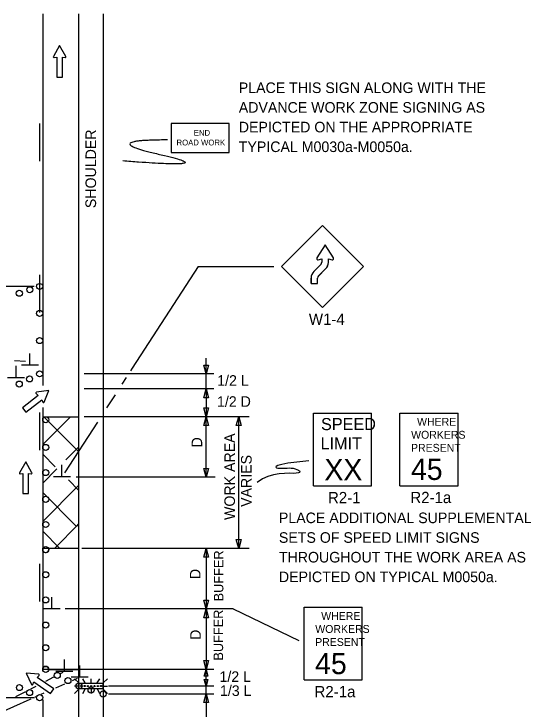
# Model space of a CAD drawing. Extents: x 16750 to 18306, y 5932 to 6925.
# Drawn here: x 17080.6 to 17422.4, y 6458.2 to 6917.6 of the extents above; entities that cross this region are included whole.
import ezdxf

# ---------------------------------------------------------------- set-up
doc = ezdxf.new("R2010")
doc.units = 0
for name, color, linetype in [('BORDER', 7, 'Continuous'), ('Level 3', 7, 'Continuous'), ('MT_SCRATCH_LEVEL_A', 7, 'Continuous'), ('MT_SCRATCH_LEVEL_E', 7, 'Continuous'), ('MT_STAGE_1A_NOTES', 7, 'Continuous'), ('PAVT_EDGE_EX', 7, 'Continuous'), ('TRAFFIC_SIGNS_PR', 7, 'Continuous'), ('TYPICAL_EX', 7, 'Continuous'), ('TYPICAL_TEXT_DIMEN_EX', 7, 'Continuous'), ('TYPICAL_TEXT_DIMEN_PR', 7, 'Continuous')]:
    doc.layers.add(name, color=color, linetype=linetype)

msp = doc.modelspace()

# ---------------------------------------------------------------- linework, layer by layer
at = {"layer": 'BORDER'}
for p, q in [((17123.59, 6564.42), (17123.59, 6917.57)), ((17123.59, 6063.18), (17123.59, 6564.42))]:
    msp.add_line(p, q, dxfattribs=at)
at = {"layer": 'Level 3'}
for p, q in [((17202.33, 6750.69), (17252.33, 6750.69)), ((17225.4, 6524.42), (17268.92, 6503.45))]:
    msp.add_line(p, q, dxfattribs=at)
at = {"layer": 'MT_SCRATCH_LEVEL_A'}
for p, q in [((17099.59, 6917.57), (17099.59, 6671.97)), ((17099.59, 6657.58), (17099.59, 6651.4)), ((17099.59, 6651.4), (17123.59, 6651.4)), ((17099.59, 6633.05), (17117.94, 6651.4)), ((17099.59, 6651.4), (17099.59, 6564.42)), ((17123.59, 6628.14), (17100.33, 6651.4)), ((17114.89, 6622.89), (17123.59, 6631.59)), ((17107.95, 6618.33), (17099.59, 6626.69)), ((17099.59, 6607.59), (17109.02, 6617.02)), ((17099.59, 6582.14), (17123.59, 6606.14)), ((17123.59, 6602.69), (17116.62, 6609.66)), ((17121.65, 6579.17), (17099.59, 6601.23)), ((17107.32, 6564.42), (17123.59, 6580.68)), ((17122.07, 6579.17), (17123.59, 6580.68)), ((17110.95, 6564.42), (17099.59, 6575.78)), ((17101.21, 6578.09), (17101.26, 6578.21)), ((17123.59, 6564.42), (17099.59, 6564.42)), ((17099.59, 6464.33), (17099.59, 6063.18))]:
    msp.add_line(p, q, dxfattribs=at)
for points in [[(17097.59, 6845.22), (17097.59, 6820.22)], [(17097.59, 6745.22), (17097.59, 6720.22)], [(17097.59, 6654.22), (17097.59, 6629.22)], [(17097.59, 6554.22), (17097.59, 6529.22)]]:
    msp.add_lwpolyline(points, dxfattribs=at)
at = {"layer": 'MT_SCRATCH_LEVEL_E'}
for p, q in [((17110.79, 6896.68), (17106.68, 6889.44)), ((17110.79, 6896.68), (17106.68, 6889.44)), ((17114.93, 6889.44), (17110.79, 6896.68)), ((17114.93, 6889.44), (17110.79, 6896.68)), ((17107.16, 6888.76), (17108.94, 6889.07)), ((17107.16, 6888.76), (17108.94, 6889.07)), ((17108.94, 6889.07), (17108.94, 6875.82)), ((17108.94, 6889.07), (17108.94, 6875.82)), ((17112.68, 6875.82), (17112.68, 6889.07)), ((17112.68, 6889.07), (17114.46, 6888.76)), ((17112.68, 6875.82), (17112.68, 6889.07)), ((17112.68, 6889.07), (17114.46, 6888.76)), ((17108.94, 6875.82), (17112.68, 6875.82)), ((17108.94, 6875.82), (17112.68, 6875.82)), ((17095.24, 6666.71), (17096.59, 6665.51)), ((17095.24, 6666.71), (17096.59, 6665.51)), ((17103.7, 6668.81), (17095.47, 6667.51)), ((17103.7, 6668.81), (17095.47, 6667.51)), ((17100.62, 6661.05), (17103.7, 6668.81)), ((17100.62, 6661.05), (17103.7, 6668.81)), ((17096.59, 6665.51), (17086.23, 6657.25)), ((17096.59, 6665.51), (17086.23, 6657.25)), ((17088.56, 6654.32), (17098.93, 6662.59)), ((17088.56, 6654.32), (17098.93, 6662.59)), ((17098.93, 6662.59), (17099.79, 6661)), ((17098.93, 6662.59), (17099.79, 6661)), ((17086.23, 6657.25), (17088.56, 6654.32)), ((17086.23, 6657.25), (17088.56, 6654.32)), ((17088.36, 6621.59), (17084.25, 6614.35)), ((17088.36, 6621.59), (17084.25, 6614.35)), ((17092.5, 6614.35), (17088.36, 6621.59)), ((17092.5, 6614.35), (17088.36, 6621.59)), ((17084.73, 6613.66), (17086.51, 6613.98)), ((17084.73, 6613.66), (17086.51, 6613.98)), ((17086.51, 6613.98), (17086.51, 6600.72)), ((17086.51, 6613.98), (17086.51, 6600.72)), ((17090.25, 6600.72), (17090.25, 6613.98)), ((17090.25, 6613.98), (17092.03, 6613.66)), ((17090.25, 6600.72), (17090.25, 6613.98)), ((17090.25, 6613.98), (17092.03, 6613.66)), ((17086.51, 6600.72), (17090.25, 6600.72)), ((17086.51, 6600.72), (17090.25, 6600.72)), ((17088.66, 6481.97), (17092.24, 6474.46)), ((17096.97, 6481.23), (17088.66, 6481.97)), ((17088.66, 6481.97), (17092.24, 6474.46)), ((17096.97, 6481.23), (17088.66, 6481.97)), ((17095.98, 6479.17), (17097.26, 6480.44)), ((17095.98, 6479.17), (17097.26, 6480.44)), ((17106.85, 6471.58), (17095.98, 6479.17)), ((17106.85, 6471.58), (17095.98, 6479.17)), ((17093.08, 6474.46), (17093.84, 6476.1)), ((17093.08, 6474.46), (17093.84, 6476.1)), ((17093.84, 6476.1), (17104.71, 6468.51)), ((17093.84, 6476.1), (17104.71, 6468.51)), ((17104.71, 6468.51), (17106.85, 6471.58)), ((17104.71, 6468.51), (17106.85, 6471.58))]:
    msp.add_line(p, q, dxfattribs=at)
for centre, start, end in [((17107.08, 6889.22), 150.4248, 279.9638), ((17107.08, 6889.22), 150.4248, 279.9638), ((17114.52, 6889.22), 260.0362, 29.7731), ((17114.52, 6889.22), 260.0362, 29.7731), ((17095.55, 6667.05), 98.9994, 228.5384), ((17095.55, 6667.05), 98.9994, 228.5384), ((17100.19, 6661.23), 208.6108, 338.3477), ((17100.19, 6661.23), 208.6108, 338.3477), ((17084.65, 6614.12), 150.4248, 279.9638), ((17084.65, 6614.12), 150.4248, 279.9638), ((17092.09, 6614.12), 260.0362, 29.7731), ((17092.09, 6614.12), 260.0362, 29.7731), ((17096.92, 6480.76), 315.105, 84.8419), ((17096.92, 6480.76), 315.105, 84.8419), ((17092.66, 6474.66), 205.4936, 335.0326), ((17092.66, 6474.66), 205.4936, 335.0326)]:
    msp.add_arc(centre, 0.463, start, end, dxfattribs=at)
at = {"layer": 'MT_STAGE_1A_NOTES'}
for points in [[(17099.8, 6564.42), (17099.59, 6564.42), (17099.59, 6484.41), (17099.61, 6484.41)], [(17103.61, 6484.41), (17113.99, 6484.41), (17123.59, 6484.41), (17123.59, 6524.42), (17123.59, 6564.42), (17103.42, 6564.42)]]:
    msp.add_lwpolyline(points, dxfattribs=at)
for centre, start, end in [((17101.61, 6563.56), 154.7227, 214.9312), ((17101.61, 6563.56), 214.9312, 25.2773), ((17101.61, 6484.41), 0, 180)]:
    msp.add_arc(centre, 2, start, end, dxfattribs=at)
at = {"layer": 'PAVT_EDGE_EX'}
for p, q in [((17139.59, 6917.57), (17139.59, 6564.42)), ((17099.59, 6579.04), (17099.59, 6564.42)), ((17099.59, 6564.42), (17099.59, 6484.41)), ((17139.59, 6564.42), (17139.59, 6484.41)), ((17139.59, 6484.41), (17139.59, 6063.18))]:
    msp.add_line(p, q, dxfattribs=at)
at = {"layer": 'TRAFFIC_SIGNS_PR'}
for p, q in [((17284.48, 6777.84), (17257.33, 6750.69)), ((17311.64, 6750.69), (17284.48, 6777.84)), ((17257.33, 6750.69), (17284.48, 6723.54)), ((17278.83, 6747.44), (17283.54, 6752.15)), ((17283.54, 6752.15), (17278.83, 6747.44)), ((17281.88, 6744.39), (17286.59, 6749.1)), ((17281.88, 6744.38), (17286.59, 6749.1)), ((17284.48, 6723.54), (17311.64, 6750.69)), ((17276.96, 6739.32), (17276.96, 6743.02)), ((17276.96, 6739.32), (17281.28, 6739.32)), ((17281.28, 6739.32), (17281.28, 6743.02)), ((17278.5, 6653.68), (17316.9, 6653.68)), ((17278.5, 6605.68), (17278.5, 6653.68)), ((17316.9, 6605.68), (17316.9, 6653.68)), ((17335.69, 6653.76), (17374.09, 6653.76)), ((17335.69, 6605.76), (17335.69, 6653.76)), ((17374.09, 6605.76), (17374.09, 6653.76)), ((17278.5, 6605.68), (17316.9, 6605.68)), ((17335.69, 6605.76), (17374.09, 6605.76)), ((17272.34, 6525.45), (17310.74, 6525.45)), ((17272.34, 6477.45), (17272.34, 6525.45)), ((17310.74, 6477.45), (17310.74, 6525.45)), ((17120.66, 6478.28), (17123.48, 6475.46)), ((17127.75, 6475.46), (17126.12, 6478.28)), ((17131.57, 6475.46), (17131.57, 6478.28)), ((17135.7, 6475.46), (17137.33, 6478.28)), ((17139.65, 6475.46), (17142.47, 6478.28)), ((17272.34, 6477.45), (17310.74, 6477.45)), ((17123.48, 6473.43), (17120.66, 6473.43)), ((17125.12, 6473.43), (17125.12, 6473.43)), ((17127.29, 6473.43), (17127.29, 6473.43)), ((17129.47, 6473.43), (17129.47, 6473.43)), ((17131.64, 6473.43), (17131.64, 6473.43)), ((17133.81, 6473.43), (17133.81, 6473.43)), ((17135.99, 6473.43), (17135.99, 6473.43)), ((17138.16, 6473.43), (17138.16, 6473.43)), ((17139.65, 6473.43), (17142.47, 6473.43)), ((17120.66, 6468.58), (17123.48, 6471.39)), ((17126.1, 6468.57), (17127.73, 6471.39)), ((17131.57, 6471.39), (17131.57, 6468.57)), ((17137.36, 6468.57), (17135.73, 6471.39)), ((17139.65, 6471.39), (17142.47, 6468.57))]:
    msp.add_line(p, q, dxfattribs=at)
for points in [[(17184.42, 6825.92), (17222.82, 6825.92), (17222.82, 6845.12), (17184.42, 6845.12)], [(17139.42, 6471.63), (17123.71, 6471.63), (17123.71, 6475.23), (17139.42, 6475.23)]]:
    msp.add_lwpolyline(points, close=True, dxfattribs=at)
for points in [[(17291.75, 6756.43), (17286.27, 6765.04), (17280.78, 6756.43)], [(17291.75, 6756.43), (17286.27, 6765.04), (17280.78, 6756.43)], [(17281.74, 6755.13), (17284.11, 6755.78), (17284.1, 6753.48)], [(17281.74, 6755.13), (17282.58, 6755.36), (17284.11, 6755.78), (17284.1, 6753.48)], [(17288.42, 6753.41), (17288.42, 6755.78), (17290.79, 6755.13)], [(17276.96, 6743.02), (17276.96, 6739.32), (17281.28, 6739.32), (17281.28, 6743.02)]]:
    msp.add_lwpolyline(points, dxfattribs=at)
for centre, radius in [((17097.59, 6737.47), 2), ((17084.16, 6733), 2), ((17091.09, 6735.29), 2), ((17097.59, 6719.69), 2), ((17097.59, 6701.69), 2), ((17097.59, 6679.72), 2), ((17084.1, 6672.97), 2), ((17090.89, 6676.37), 2), ((17101.61, 6649.4), 2), ((17101.61, 6631.09), 2), ((17101.61, 6614.48), 2), ((17101.61, 6596.79), 2), ((17101.61, 6580.18), 2), ((17101.61, 6563.56), 2), ((17101.61, 6546.95), 2), ((17101.61, 6530.34), 2), ((17101.61, 6513.73), 2), ((17101.61, 6498.72), 2), ((17101.61, 6484.41), 2), ((17109.22, 6480.45), 2), ((17116.29, 6477.04), 2), ((17084.26, 6472.42), 2), ((17123.59, 6473.43), 2), ((17125.14, 6473.43), 0.379), ((17127.29, 6473.43), 0.379), ((17129.47, 6473.43), 0.379), ((17131.56, 6470.8), 2), ((17131.64, 6473.43), 0.379), ((17133.81, 6473.43), 0.379), ((17135.99, 6473.43), 0.379), ((17138.16, 6473.43), 0.379), ((17090.92, 6469.08), 2), ((17139.54, 6468.17), 2), ((17097.59, 6465.75), 2)]:
    msp.add_circle(centre, radius, dxfattribs=at)
for centre, radius, start, end in [((17281.52, 6755.96), 0.864, 147.5204, 285.3986), ((17281.52, 6755.96), 0.866, 147.5288, 285.3852), ((17282.25, 6753.48), 1.85, 314.2125, 0), ((17282.25, 6753.48), 1.85, 314.2123, 0.1238), ((17282.25, 6753.48), 6.17, 314.2125, 359.3819), ((17282.25, 6753.48), 6.17, 314.7687, 359.3755), ((17291.02, 6755.96), 0.866, 254.6799, 32.2804), ((17283.13, 6743.02), 6.17, 134.2125, 180), ((17283.13, 6743.02), 6.17, 134.2125, 180), ((17283.13, 6743.02), 6.17, 134.2117, 180), ((17283.13, 6743.02), 1.85, 132.372, 180), ((17283.13, 6743.02), 1.85, 134.2125, 180)]:
    msp.add_arc(centre, radius, start, end, dxfattribs=at)
msp.add_open_spline([(17182.06, 6834.28), (17134.83, 6834.28), (17219.85, 6814.94), (17152.52, 6820.43)], degree=2, dxfattribs=at)
at = {"layer": 'TYPICAL_EX'}
for p, q in [((17091.13, 6685.38), (17091.13, 6693.17)), ((17082.04, 6677.17), (17082.04, 6684.95)), ((17096.76, 6685.38), (17085.51, 6685.38)), ((17087.66, 6677.17), (17076.41, 6677.17)), ((17112.33, 6611.74), (17112.33, 6619.53)), ((17117.95, 6611.74), (17106.7, 6611.74)), ((17105.59, 6524.42), (17105.59, 6532.2)), ((17111.21, 6524.42), (17099.96, 6524.42)), ((17113.99, 6483.07), (17113.99, 6490.86)), ((17124.08, 6479.32), (17124.08, 6487.1)), ((17119.61, 6483.07), (17108.36, 6483.07)), ((17129.71, 6479.32), (17118.46, 6479.32))]:
    msp.add_line(p, q, dxfattribs=at)
at = {"layer": 'TYPICAL_TEXT_DIMEN_PR'}
for p, q in [((17202.33, 6750.69), (17158.75, 6683.41)), ((17093.86, 6737.47), (16962.49, 6737.47)), ((17207.59, 6669.72), (17207.59, 6689.99)), ((17081.03, 6688.49), (17088.3, 6688.18)), ((17207.59, 6679.69), (17206.02, 6685.55)), ((17206.02, 6685.55), (17207.59, 6685.55)), ((17207.59, 6685.55), (17209.16, 6685.55)), ((17209.16, 6685.55), (17207.59, 6679.69)), ((17212.59, 6679.72), (17126.9, 6679.72)), ((17158.75, 6683.41), (17157.68, 6681.76)), ((17154.86, 6677.4), (17151.91, 6672.85)), ((17212.59, 6669.72), (17126.9, 6669.72)), ((17147.41, 6665.9), (17141.84, 6657.3)), ((17206.02, 6663.86), (17207.59, 6669.72)), ((17207.59, 6669.72), (17209.16, 6663.86)), ((17207.59, 6669.72), (17207.59, 6651.4)), ((17207.59, 6663.86), (17206.02, 6663.86)), ((17209.16, 6663.86), (17207.59, 6663.86)), ((17207.59, 6651.4), (17206.02, 6657.26)), ((17206.02, 6657.26), (17207.59, 6657.26)), ((17207.59, 6657.26), (17209.16, 6657.26)), ((17209.16, 6657.26), (17207.59, 6651.4)), ((17135.72, 6647.86), (17114.04, 6614.39)), ((17236.14, 6651.4), (17126.9, 6651.4)), ((17206.02, 6645.54), (17207.59, 6651.4)), ((17207.59, 6611.4), (17207.59, 6651.4)), ((17207.59, 6651.4), (17209.16, 6645.54)), ((17227.56, 6645.54), (17229.13, 6651.4)), ((17229.13, 6651.4), (17230.7, 6645.54)), ((17229.13, 6564.42), (17229.13, 6651.4)), ((17207.59, 6645.54), (17206.02, 6645.54)), ((17209.16, 6645.54), (17207.59, 6645.54)), ((17229.13, 6645.54), (17227.56, 6645.54)), ((17230.7, 6645.54), (17229.13, 6645.54)), ((17207.59, 6611.4), (17206.02, 6617.26)), ((17206.02, 6617.26), (17207.59, 6617.26)), ((17207.59, 6617.26), (17209.16, 6617.26)), ((17209.16, 6617.26), (17207.59, 6611.4)), ((17213.5, 6611.4), (17121.69, 6611.4)), ((17229.13, 6564.42), (17227.56, 6570.28)), ((17227.56, 6570.28), (17229.13, 6570.28)), ((17229.13, 6570.28), (17230.7, 6570.28)), ((17230.7, 6570.28), (17229.13, 6564.42)), ((17236.14, 6564.42), (17125.47, 6564.42)), ((17206.02, 6558.56), (17207.59, 6564.42)), ((17207.59, 6564.42), (17209.16, 6558.56)), ((17207.59, 6564.42), (17207.59, 6484.41)), ((17207.59, 6558.56), (17206.02, 6558.56)), ((17209.16, 6558.56), (17207.59, 6558.56)), ((17207.59, 6524.42), (17206.02, 6530.28)), ((17206.02, 6530.28), (17207.59, 6530.28)), ((17207.59, 6530.28), (17209.16, 6530.28)), ((17209.16, 6530.28), (17207.59, 6524.42)), ((17225.4, 6524.42), (17114.46, 6524.42)), ((17206.02, 6518.55), (17207.59, 6524.42)), ((17207.59, 6524.42), (17209.16, 6518.55)), ((17207.59, 6518.55), (17206.02, 6518.55)), ((17209.16, 6518.55), (17207.59, 6518.55)), ((17207.59, 6484.41), (17206.02, 6490.28)), ((17206.02, 6490.28), (17207.59, 6490.28)), ((17207.59, 6490.28), (17209.16, 6490.28)), ((17209.16, 6490.28), (17207.59, 6484.41)), ((17139.59, 6484.41), (17099.59, 6484.41)), ((17111.45, 6481.76), (17113.18, 6482.66)), ((17212.59, 6484.41), (17139.59, 6484.41)), ((17206.41, 6480.02), (17207.59, 6484.41)), ((17207.59, 6484.41), (17208.77, 6480.02)), ((17207.59, 6468.36), (17207.59, 6483.76)), ((17101.73, 6476.74), (17106.91, 6479.41)), ((17119.22, 6477.16), (17122.64, 6478.68)), ((17207.59, 6480.02), (17206.41, 6480.02)), ((17207.59, 6473.43), (17206.41, 6477.82)), ((17206.41, 6477.82), (17207.59, 6477.82)), ((17208.77, 6480.02), (17207.59, 6480.02)), ((17207.59, 6477.82), (17208.77, 6477.82)), ((17208.77, 6477.82), (17207.59, 6473.43)), ((17091.67, 6471.54), (17095.24, 6473.39)), ((17108.35, 6472.34), (17114.3, 6474.98)), ((17212.59, 6473.43), (17143.11, 6473.43)), ((17081.83, 6466.46), (17088.45, 6469.88)), ((17098.63, 6468.03), (17100.54, 6468.88)), ((17143.11, 6468.36), (17212.59, 6468.36)), ((17206.02, 6462.49), (17207.59, 6468.36)), ((17207.59, 6468.36), (17207.59, 6428.36)), ((17207.59, 6468.36), (17209.16, 6462.49)), ((16962.49, 6465.75), (17094.29, 6465.75)), ((17001.57, 6424.99), (17091.23, 6464.75)), ((17091.23, 6464.75), (17091.95, 6465.07)), ((17094.54, 6466.22), (17095.2, 6466.51)), ((17207.59, 6462.49), (17206.02, 6462.49)), ((17209.16, 6462.49), (17207.59, 6462.49))]:
    msp.add_line(p, q, dxfattribs=at)
msp.add_open_spline([(17275.57, 6622.31), (17250.98, 6619.98), (17253.73, 6615.93), (17265.61, 6618.97), (17274.89, 6612.05), (17250.29, 6615.37), (17241.3, 6607.83)], degree=3, dxfattribs=at)

# ---------------------------------------------------------------- texts
at = {"layer": 'TRAFFIC_SIGNS_PR'}
for s, height, p in [('PLACE THIS SIGN ALONG WITH THE', 7, (17229.18, 6865.29)), ('ADVANCE WORK ZONE SIGNING AS', 7, (17229.18, 6852.29)), ('DEPICTED ON THE APPROPRIATE', 7, (17229.18, 6839.29)), ('END', 3.831, (17199.42, 6837.05)), ('ROAD WORK', 3.831, (17188.03, 6830.66)), ('TYPICAL M0030a-M0050a.', 7, (17229.18, 6826.29)), ('W1-4', 7.44, (17275.49, 6712.1)), ('SPEED', 8, (17283.53, 6642.54)), ('WHERE', 5.2, (17347, 6645.45)), ('WORKERS', 5.2, (17343.07, 6636.85)), ('LIMIT', 8, (17283.2, 6629.74)), ('PRESENT', 5.2, (17343.01, 6628.25)), ('XX', 14.031, (17285.8, 6609.43)), ('45', 14.031, (17343, 6609.62)), ('R2-1', 7.44, (17288.1, 6594.24)), ('R2-1a', 7.44, (17342.54, 6594.32)), ('PLACE ADDITIONAL SUPPLEMENTAL', 7, (17255.69, 6581.07)), ('SETS OF SPEED LIMIT SIGNS', 7, (17255.69, 6568.07)), ('THROUGHOUT THE WORK AREA AS', 7, (17255.69, 6555.07)), ('DEPICTED ON TYPICAL M0050a.', 7, (17255.69, 6542.07)), ('WHERE', 5.2, (17283.65, 6517.14)), ('WORKERS', 5.2, (17279.73, 6508.54)), ('PRESENT', 5.2, (17279.66, 6499.94)), ('45', 14.031, (17279.65, 6481.31)), ('R2-1a', 7.44, (17279.2, 6466.01))]:
    msp.add_text(s, height=height, dxfattribs=at).set_placement(p)
at = {"layer": 'TYPICAL_TEXT_DIMEN_EX'}
msp.add_text('SHOULDER', height=7, rotation=90, dxfattribs=at).set_placement((17134.87, 6789.22))
at = {"layer": 'TYPICAL_TEXT_DIMEN_PR'}
for s, p in [('1/2 L', (17214.94, 6671.86)), ('1/2 D', (17214.8, 6657.93)), ('1/2 L', (17216.41, 6476.13)), ('1/3 L', (17216.76, 6466.86))]:
    msp.add_text(s, height=7, dxfattribs=at).set_placement(p)
for s, height, p in [('WORK AREA', 7, (17226.65, 6583.16)), ('D', 7, (17205.03, 6631.09)), ('VARIES', 7, (17237.65, 6591.8)), ('BUFFER', 6.3, (17219.01, 6529.37)), ('D', 7, (17203.88, 6544.07)), ('BUFFER', 6.3, (17218.82, 6490.23)), ('D', 7, (17204.07, 6503.93))]:
    msp.add_text(s, height=height, rotation=90, dxfattribs=at).set_placement(p)

doc.saveas('drawing.dxf')
